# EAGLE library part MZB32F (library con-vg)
CONNECTOR male, 32 pins, single, type F, rows BZ, grid 5.08 mm
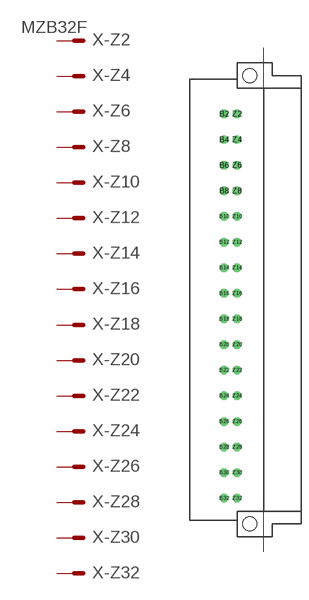
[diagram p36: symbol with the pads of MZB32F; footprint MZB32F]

Designator prefix X; gates -Z2=MVAL -Z4=MAL -Z6=MAL -Z8=MAL -Z10=MAL -Z12=MAL -Z14=MAL -Z16=MAL -Z18=MAL -Z20=MAL -Z22=MAL -Z24=MAL -Z26=MAL -Z28=MAL -Z30=MAL -Z32=MAL -B2=MVAL -B4=MAL -B6=MAL -B8=MAL -B10=MAL -B12=MAL -B14=MAL -B16=MAL -B18=MAL -B20=MAL -B22=MAL -B24=MAL -B26=MAL -B28=MAL -B30=MAL -B32=MAL

## MZB32F  [MZB32F]
B2  -B2:S  pas
B4  -B4:S  pas
B6  -B6:S  pas
B8  -B8:S  pas
B10  -B10:S  pas
B12  -B12:S  pas
B14  -B14:S  pas
B16  -B16:S  pas
B18  -B18:S  pas
B20  -B20:S  pas
B22  -B22:S  pas
B24  -B24:S  pas
B26  -B26:S  pas
B28  -B28:S  pas
B30  -B30:S  pas
B32  -B32:S  pas
Z2  -Z2:S  pas
Z4  -Z4:S  pas
Z6  -Z6:S  pas
Z8  -Z8:S  pas
Z10  -Z10:S  pas
Z12  -Z12:S  pas
Z14  -Z14:S  pas
Z16  -Z16:S  pas
Z18  -Z18:S  pas
Z20  -Z20:S  pas
Z22  -Z22:S  pas
Z24  -Z24:S  pas
Z26  -Z26:S  pas
Z28  -Z28:S  pas
Z30  -Z30:S  pas
Z32  -Z32:S  pas

## Footprint MZB32F (pad centres in mm)
CONNECTOR male, 32 pins, type F, rows BZ, grid 5.08 mm
drill 1.118 octagon: B2 -5.08,36.83; B4 -5.08,31.75; B6 -5.08,26.67; B8 -5.08,21.59; B10 -5.08,16.51; B12 -5.08,11.43; B14 -5.08,6.35; B16 -5.08,1.27; B18 -5.08,-3.81; B20 -5.08,-8.89; B22 -5.08,-13.97; B24 -5.08,-19.05; B26 -5.08,-24.13; B28 -5.08,-29.21; B30 -5.08,-34.29; B32 -5.08,-39.37; Z2 -2.54,36.83; Z4 -2.54,31.75; Z6 -2.54,26.67; Z8 -2.54,21.59; Z10 -2.54,16.51; Z12 -2.54,11.43; Z14 -2.54,6.35; Z16 -2.54,1.27; Z18 -2.54,-3.81; Z20 -2.54,-8.89; Z22 -2.54,-13.97; Z24 -2.54,-19.05; Z26 -2.54,-24.13; Z28 -2.54,-29.21; Z30 -2.54,-34.29; Z32 -2.54,-39.37
hole 2.794 at 0,44.45
hole 2.794 at 0,-44.45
